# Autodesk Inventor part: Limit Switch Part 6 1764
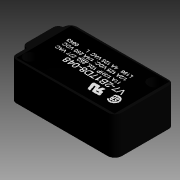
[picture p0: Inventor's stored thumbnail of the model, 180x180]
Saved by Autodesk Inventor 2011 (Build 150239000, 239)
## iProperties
Shininess: 0.0
Created: 2002-01
Part Number: Limit Switch Part 6 1764
Document SubType Name: Modeling
Density: 1 g/cm^3
Density: 0.0
Volumn: 0.0
Area: 0.0
PropertySet Name: Model Information
Control State: 0
Master: False
Checked Out: False
Author: Administrator
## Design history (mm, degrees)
node "Base1"
sketch "Sketch3"
  geometry: L1 (25.274, -15.222)-(-1.011, -15.36); L2 (-1.011, -15.36)-(-1.089, -0.521); L3 (-1.089, -0.521)-(25.196, -0.383); L4 (25.196, -0.383)-(25.274, -15.222)
  constraints: 2 other
feature "Decal1" sketch "Sketch3"
node "Image2"
